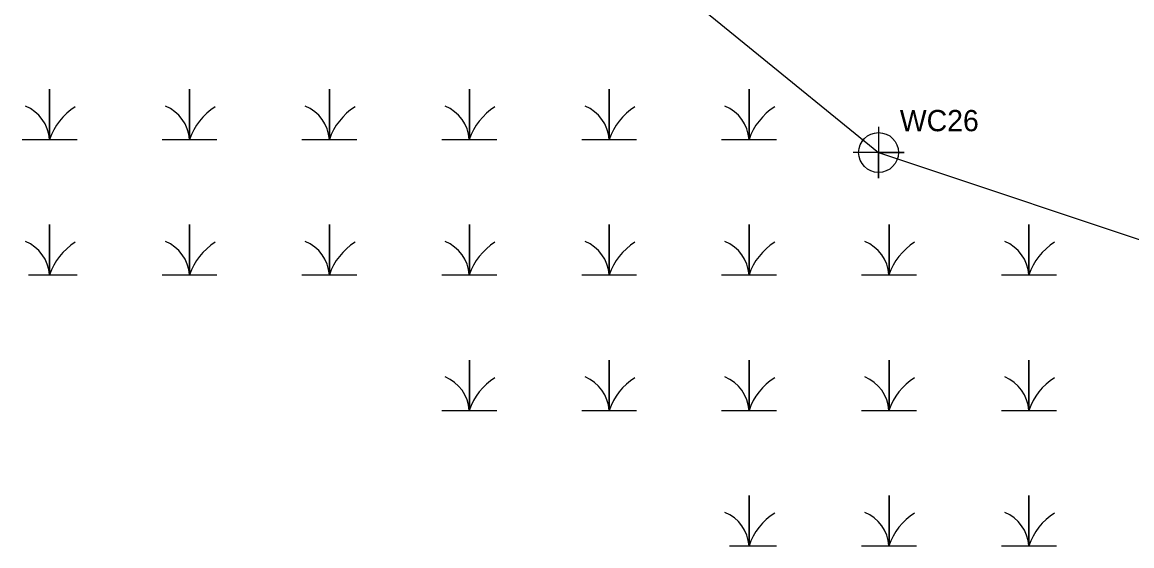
# Model space of a CAD drawing. Extents: x 2138832 to 2141061, y 149156 to 150675.
# Drawn here: x 2140516.5 to 2140647, y 149275.2 to 149336.8 of the extents above; entities that cross this region are included whole.
import ezdxf

# ---------------------------------------------------------------- set-up
doc = ezdxf.new("R2010")
doc.units = 0
for name, color, linetype in [('Exist Environmental Wetland Boundary', 7, 'Continuous'), ('Exist Environmental Wetland Boundary Cogo Number', 7, 'Continuous'), ('Exist Environmental Wetland Boundary Cogo Point CELL', 7, 'Continuous')]:
    doc.layers.add(name, color=color, linetype=linetype)

msp = doc.modelspace()

# ---------------------------------------------------------------- linework, layer by layer
at = {"layer": 'Exist Environmental Wetland Boundary'}
msp.add_lwpolyline([(2140585.59, 149347.19), (2140617.17, 149321.45), (2140653.35, 149309.39)], dxfattribs=at)
at = {"layer": 'Exist Environmental Wetland Boundary Cogo Point CELL'}
msp.add_line((2140615.18, 149322.98), (2140615.31, 149322.98), dxfattribs=at)
for points in [[(2140516.47, 149322.98), (2140519.69, 149322.98), (2140519.69, 149328.89), (2140519.69, 149322.98), (2140522.92, 149322.98)], [(2140532.92, 149322.98), (2140536.14, 149322.98), (2140536.14, 149328.89), (2140536.14, 149322.98), (2140539.37, 149322.98)], [(2140549.37, 149322.98), (2140552.6, 149322.98), (2140552.6, 149328.89), (2140552.6, 149322.98), (2140555.82, 149322.98)], [(2140565.82, 149322.98), (2140569.05, 149322.98), (2140569.05, 149328.89), (2140569.05, 149322.98), (2140572.27, 149322.98)], [(2140582.27, 149322.98), (2140585.5, 149322.98), (2140585.5, 149328.89), (2140585.5, 149322.98), (2140588.72, 149322.98)], [(2140598.72, 149322.98), (2140601.95, 149322.98), (2140601.95, 149328.89), (2140601.95, 149322.98), (2140605.18, 149322.98)], [(2140617.17, 149324.45), (2140617.17, 149318.45), (2140617.17, 149321.45), (2140620.17, 149321.45), (2140614.17, 149321.45)], [(2140517.22, 149307.06), (2140519.69, 149307.06), (2140519.69, 149312.98), (2140519.69, 149307.06), (2140522.92, 149307.06)], [(2140532.92, 149307.06), (2140536.14, 149307.06), (2140536.14, 149312.98), (2140536.14, 149307.06), (2140539.37, 149307.06)], [(2140549.37, 149307.06), (2140552.6, 149307.06), (2140552.6, 149312.98), (2140552.6, 149307.06), (2140555.82, 149307.06)], [(2140565.82, 149307.06), (2140569.05, 149307.06), (2140569.05, 149312.98), (2140569.05, 149307.06), (2140572.27, 149307.06)], [(2140582.27, 149307.06), (2140585.5, 149307.06), (2140585.5, 149312.98), (2140585.5, 149307.06), (2140588.72, 149307.06)], [(2140598.72, 149307.06), (2140601.95, 149307.06), (2140601.95, 149312.98), (2140601.95, 149307.06), (2140605.18, 149307.06)], [(2140615.18, 149307.06), (2140618.4, 149307.06), (2140618.4, 149312.98), (2140618.4, 149307.06), (2140621.63, 149307.06)], [(2140631.63, 149307.06), (2140634.85, 149307.06), (2140634.85, 149312.98), (2140634.85, 149307.06), (2140638.08, 149307.06)], [(2140565.82, 149291.14), (2140569.05, 149291.14), (2140569.05, 149297.06), (2140569.05, 149291.14), (2140572.27, 149291.14)], [(2140582.27, 149291.14), (2140585.5, 149291.14), (2140585.5, 149297.06), (2140585.5, 149291.14), (2140588.72, 149291.14)], [(2140598.72, 149291.14), (2140601.95, 149291.14), (2140601.95, 149297.06), (2140601.95, 149291.14), (2140605.18, 149291.14)], [(2140615.18, 149291.14), (2140618.4, 149291.14), (2140618.4, 149297.06), (2140618.4, 149291.14), (2140621.63, 149291.14)], [(2140631.63, 149291.14), (2140634.85, 149291.14), (2140634.85, 149297.06), (2140634.85, 149291.14), (2140638.08, 149291.14)], [(2140599.66, 149275.22), (2140601.95, 149275.22), (2140601.95, 149281.14), (2140601.95, 149275.22), (2140605.18, 149275.22)], [(2140615.18, 149275.22), (2140618.4, 149275.22), (2140618.4, 149281.14), (2140618.4, 149275.22), (2140621.63, 149275.22)], [(2140631.63, 149275.22), (2140634.85, 149275.22), (2140634.85, 149281.14), (2140634.85, 149275.22), (2140638.08, 149275.22)]]:
    msp.add_lwpolyline(points, dxfattribs=at)
msp.add_circle((2140617.17, 149321.45), 2.34, dxfattribs=at)
for centre, radius, start, end in [((2140515.09, 149322.64), 4.61, 4.1403, 67.535), ((2140526.53, 149320.7), 7.21, 122.1274, 161.6222), ((2140531.55, 149322.64), 4.61, 4.1403, 67.535), ((2140542.99, 149320.7), 7.21, 122.1274, 161.6222), ((2140548, 149322.64), 4.61, 4.1403, 67.535), ((2140559.44, 149320.7), 7.21, 122.1274, 161.6222), ((2140564.45, 149322.64), 4.61, 4.1403, 67.535), ((2140575.89, 149320.7), 7.21, 122.1274, 161.6222), ((2140580.9, 149322.64), 4.61, 4.1403, 67.535), ((2140592.34, 149320.7), 7.21, 122.1274, 161.6222), ((2140597.35, 149322.64), 4.61, 4.1403, 67.535), ((2140608.79, 149320.7), 7.21, 122.1274, 161.6222), ((2140515.09, 149306.73), 4.61, 4.1403, 67.535), ((2140526.53, 149304.79), 7.21, 122.1274, 161.6222), ((2140531.55, 149306.73), 4.61, 4.1403, 67.535), ((2140542.99, 149304.79), 7.21, 122.1274, 161.6222), ((2140548, 149306.73), 4.61, 4.1403, 67.535), ((2140559.44, 149304.79), 7.21, 122.1274, 161.6222), ((2140564.45, 149306.73), 4.61, 4.1403, 67.535), ((2140575.89, 149304.79), 7.21, 122.1274, 161.6222), ((2140580.9, 149306.73), 4.61, 4.1403, 67.535), ((2140592.34, 149304.79), 7.21, 122.1274, 161.6222), ((2140597.35, 149306.73), 4.61, 4.1403, 67.535), ((2140608.79, 149304.79), 7.21, 122.1274, 161.6222), ((2140613.8, 149306.73), 4.61, 4.1403, 67.535), ((2140625.24, 149304.79), 7.21, 122.1274, 161.6222), ((2140630.25, 149306.73), 4.61, 4.1403, 67.535), ((2140641.69, 149304.79), 7.21, 122.1274, 161.6222), ((2140564.45, 149290.81), 4.61, 4.1403, 67.535), ((2140575.89, 149288.87), 7.21, 122.1274, 161.6222), ((2140580.9, 149290.81), 4.61, 4.1403, 67.535), ((2140592.34, 149288.87), 7.21, 122.1274, 161.6222), ((2140597.35, 149290.81), 4.61, 4.1403, 67.535), ((2140608.79, 149288.87), 7.21, 122.1274, 161.6222), ((2140613.8, 149290.81), 4.61, 4.1403, 67.535), ((2140625.24, 149288.87), 7.21, 122.1274, 161.6222), ((2140630.25, 149290.81), 4.61, 4.1403, 67.535), ((2140641.69, 149288.87), 7.21, 122.1274, 161.6222), ((2140597.35, 149274.89), 4.61, 4.1403, 67.535), ((2140613.8, 149274.89), 4.61, 4.1403, 67.535), ((2140630.25, 149274.89), 4.61, 4.1403, 67.535), ((2140608.79, 149272.95), 7.21, 122.1274, 161.6222), ((2140625.24, 149272.95), 7.21, 122.1274, 161.6222), ((2140641.69, 149272.95), 7.21, 122.1274, 161.6222)]:
    msp.add_arc(centre, radius, start, end, dxfattribs=at)

# ---------------------------------------------------------------- texts
at = {"layer": 'Exist Environmental Wetland Boundary Cogo Number'}
msp.add_text('WC26', height=2.5, dxfattribs=at).set_placement((2140619.67, 149323.95))

doc.saveas('drawing.dxf')
